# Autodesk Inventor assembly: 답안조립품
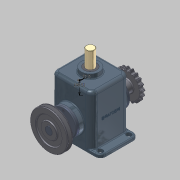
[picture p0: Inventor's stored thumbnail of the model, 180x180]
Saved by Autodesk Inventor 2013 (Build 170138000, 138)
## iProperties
Created: 2015-01
Part Number: 답안조립품
Document SubType Name: Assembly
Designer: Administrator
Mass: 14861.6 g
Surface Area: 4424.06 cm^2
Volume: 1987.46 cm^3
Density: 7.47768 g/cm^3
Author: Administrator
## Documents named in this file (15)
- C:\Users\Administrator\Desktop\350106V1031\답안조립품.iam
- C:\Users\Administrator\Desktop\350106V1031\본체.ipt
- C:\Users\Administrator\Desktop\350106V1031\커버.ipt
- C:\Users\Administrator\Desktop\350106V1031\오일실.ipt
- C:\Users\Administrator\Desktop\350106V1031\M4x0.5.ipt
- C:\Users\Administrator\Desktop\350106V1031\베어링 6205.ipt
- C:\Users\Administrator\Desktop\350106V1031\편심축.ipt
- C:\Users\Administrator\Desktop\350106V1031\멈춤링.ipt
- C:\Users\Administrator\Desktop\350106V1031\키 8x8.ipt
- C:\Users\Administrator\Desktop\350106V1031\V-벨트풀리.ipt
- C:\Users\Administrator\Desktop\350106V1031\체인 스프로킷.ipt
- C:\Users\Administrator\Desktop\350106V1031\멈춤나사 M5x0.5.ipt
- C:\Users\Administrator\Desktop\350106V1031\부시.ipt
- C:\Users\Administrator\Desktop\350106V1031\슬라이드.ipt
- C:\Users\Administrator\Desktop\350106V1031\7-가변스프링.ipt
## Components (9 placed, 4 different names)
1. V-벨트풀리:1 — 플러쉬:2
2. 5-체인 스프로킷:1 — 플러쉬:1
3. 7-가변스프링:1
4. M4x0.5:2
5. M4x0.5:3
6. M4x0.5:4
7. M4x0.5:1
8. M4x0.5:5
9. M4x0.5:6
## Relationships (2: Flush 2)
- 플러쉬:1 [Flush]: 5-체인 스프로킷:1
- 플러쉬:2 [Flush]: V-벨트풀리:1
